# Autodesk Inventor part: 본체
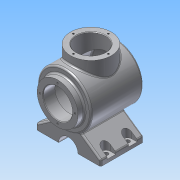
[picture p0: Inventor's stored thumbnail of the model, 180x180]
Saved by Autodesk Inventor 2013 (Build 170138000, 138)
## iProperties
Created: 2017-04
Part Number: 본체
Material: 알루미늄 6061
Document SubType Name: Modeling
Designer: Administrator
Density: 2.71 g/cm^3
Mass: 1670.76 g
Surface Area: 1066.88 cm^2
Volume: 616.516 cm^3
Author: Administrator
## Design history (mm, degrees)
sketch "스케치1"
  geometry: L1 (-60, 0)-(60, 0); L2 (-60, 27)-(-60, 38); L3 (-60, 38)-(-48, 38); L4 (-48, 38)-(-48, 50); L5 (-48, 50)-(48.336, 50); L6 (41.916, 40)-(-38, 40); L7 (-38, 40)-(-38, 27); L8 (-38, 27)-(-60, 27); A1 r 113 centre (-53, 0) between (60, 0) and (48.336, 50); A2 r 103 centre (-53, 0) between (50, 0) and (41.916, 40); 2 further points
  constraints: 16 end point, 4 point on circle, 3 parallel, 2 centre point, 2 perpendicular, 2 point on line, 1 coincident, 1 horizontal, 1 midpoint, 1 vertical alignment, 1 other
  dimensions: "d0" = 113 radius of A1; "d2" = 120 distance from line of L1.end L2; "d3" = 76 diameter of L3 L1; "d4" = 100 diameter of L5 L1; "d5" = 12 distance between parallel lines of L4 L2; "d6" = 54 diameter of L8 L1; "d7" = 80 diameter of L6 L1; "d8" = 10 radial gap between concentric circles of A1 A2
revolve "회전1" sketch "스케치1" stored, may be unused: angle "d9" = 90 deg
node "작업 평면1"
sketch "스케치5"
  geometry: L1 (-82, 70)-(-82, -70) reference; L2 (-82, -60)-(-72, -60); L3 (-72, -60)-(-38.229, -11.77); L4 (-38.229, 11.77)-(-72, 60); L5 (-72, 60)-(-82, 60); A1 r 40 centre (0, 0) between (-38.229, -11.77) and (-38.229, 11.77) reference; 1 further point
  constraints: 8 end point, 2 perpendicular, 2 point on circle, 2 point on line, 1 vertical alignment
  dimensions: "d14" = 120 distance between parallel lines of L5 L2; "d16" = 60 distance from line of point (0, 0) L2; "d17" = 55 deg angle of L2 L3; "d18" = 55 deg angle of L5 L4; "d19" = 10 distance of L2.start L2.end
extrude "돌출1" join sketch "스케치5" stored distance "d20" = 80; taper "d21" = 0 deg
sketch "스케치6"
  geometry: L1 (-60, -82)-(60, -82) reference; C1 r 18 at (0, -82); A1 r 50 centre (0, 0) between (-21.584, -45.101) and (21.584, -45.101) reference; 1 further point
  constraints: 1 centre point, 1 coincident, 1 midpoint, 1 vertical alignment
  dimensions: "d22" = 36 diameter of C1
extrude "돌출2" cut sketch "스케치6" stored distance "d24" = 80; taper "d25" = 0 deg
node "작업 평면3"
sketch "스케치7"
  geometry: L1 (-40, 21.584)-(-40, 60) reference; L2 (40, 60)-(40, 21.584) reference; L3 (40, 60)-(-40, 60) reference; L4 (-12, 60)-(-12, 50); L5 (-28, 50)-(-28, 60); C1 r 4 at (-20, 50); A1 r 8 centre (-20, 50) between (-28, 50) and (-12, 50); 1 further point
  constraints: 4 end point, 2 centre point, 2 horizontal alignment, 2 point on circle, 2 point on line, 2 tangent, 1 coincident, 1 parallel, 1 perpendicular
  dimensions: "d27" = 20 distance from line of L1 C1.centre; "d28" = 8 radius of A1; "d29" = 8 diameter of C1; "d30" = 10 distance from line of L3 A1.centre
extrude "돌출3" cut sketch "스케치7" stored distance "d31" = 80; taper "d32" = 0 deg
sketch "스케치9"
  geometry: L1 (52, 32)-(52, 42) reference; L2 (68, 42)-(68, 32) reference; L3 (52, 42)-(68, 42); A1 r 8 centre (60, 32) between (52, 32) and (68, 32) reference; 1 further point
  constraints: 2 end point, 1 perpendicular
extrude "돌출4" join sketch "스케치9" distance "d33" = 6; taper "d34" = 0 deg
sketch "스케치11"
  geometry: C1 r 4 at (60, -32); A1 r 8 centre (60, -32) between (68, -32) and (52, -32) reference; 1 further point
  constraints: 1 centre point, 1 coincident
  dimensions: "d35" = 8 diameter of C1
extrude "돌출5" cut sketch "스케치11" stored distance "d37" = 6; taper "d38" = 0 deg
node "작업 평면4"
sketch "스케치13"
  geometry: L1 (48, 50)-(48, -50) reference; C1 r 38 at (-2, 0); 1 further point
  constraints: 1 centre point, 1 horizontal alignment
  dimensions: "d40" = 50 distance from line of L1 C1.centre; "d41" = 76 diameter of C1
extrude "돌출6" join sketch "스케치13" stored distance "d42" = 6; taper "d43" = 0 deg
fillet "모깎기1" dims "d44" = 3
fillet "모깎기2" dims "d45" = 3
fillet "모깎기3" dims "d46" = 3
fillet "모깎기4" dims "d47" = 3
fillet "모깎기5" dims "d48" = 3
sketch "스케치15"
  geometry: C1 r 38 at (0, 0) reference; C2 r 27 at (0, 0); 1 further point
  constraints: 1 centre point
  dimensions: "d49" = 54 diameter of C2
extrude "돌출7" cut sketch "스케치15" stored distance "d51" = 6; taper "d52" = 0 deg
chamfer "모따기1" distance "d53" = 1; stored, may be unused: second distance "d54" = 2, angle "d55" = 45 deg
sketch "스케치16"
  geometry: C1 r 38 at (0, 0) reference; 1 further point
  constraints: 1 vertical alignment
  dimensions: "d56" = 32.5 distance of C1.centre point (0, 32.5)
hole "구멍1" sketch "스케치16" at (0, 32.5) diameter "d57" = 3.242; stored, may be unused: countersink angle "d61" = 90 deg, drill point angle "d63" = 118 deg; dims "d58" = 8, "d59" = 4, "d60" = 2, "d62" = 10
sketch "스케치17"
  geometry: C1 r 38 at (0, 0) reference; 2 further points
  constraints: 1 vertical alignment
  dimensions: "d67" = 32.5 distance of C1.centre point (0, 32.5)
hole "구멍2" sketch "스케치17" at (0, 32.5) diameter "d68" = 3.242; stored, may be unused: countersink angle "d72" = 90 deg, drill point angle "d74" = 118 deg; dims "d69" = 8, "d70" = 4, "d71" = 2, "d73" = 10
node "작업 평면5"
sketch "스케치18"
  geometry: 2 further points
  constraints: 1 coincident, 1 other
feature "엠보싱1" sketch "스케치18" dims "d0" = 113, "d2" = 120, "d3" = 76, "d4" = 100, "d5" = 12, "d6" = 54, "d7" = 80, "d8" = 10, "d14" = 120, "d16" = 60, "d17" = 55 deg, "d18" = 55 deg, "d19" = 10, "d79" = 0.5, "d80" = 0
node "솔리드1"
mirror "대칭1"
mirror "대칭2"
mirror "대칭3"
pattern_circular "원형 패턴1" dims angle "d65" = 360 deg
pattern_circular "원형 패턴2" dims angle "d76" = 360 deg
other parameters: "d10" = -82, "d26" = -49.5, "d39" = 65, "d78" = 117.25
